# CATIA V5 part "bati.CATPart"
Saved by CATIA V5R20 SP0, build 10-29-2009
Part number: bati
Bounding box of the stored display mesh (mm): x -30 to 10, y -75 to 75, z 0 to 70
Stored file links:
  D:\Dropbox\IAO_2011\MMS_GR2\IAO_2011_1491_mcabanel\IAO_2011_1491_mcabanel\bati.CATPart
  U:\2A\IAO\Projet\ass\kin\IAO_mcabanel.CATProduct
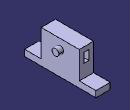
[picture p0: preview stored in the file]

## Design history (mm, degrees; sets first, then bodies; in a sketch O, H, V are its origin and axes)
Set1
  Point1: linked copy from another document
  Point2: linked copy from another document
Body1 (main body)
  Sketch1 on yz-plane, origin (0, 0, 0), H (0, 1, 0), V (0, 0, 1)
    point P1 (-75, 0)
    line L1 (-75, 0) -> (75, 0)
    line L2 (75, 0) -> (75, 13)
    line L3 (75, 13) -> (40, 13)
    line L4 (40, 13) -> (40, 70)
    line L5 (40, 70) -> (-40, 70)
    line L6 (-40, 70) -> (-40, 13)
    point P7 (-40, 13)
    line L7 (-40, 13) -> (-75, 13)
    line L8 (-75, 13) -> (-75, 0)
    distance L8 L2 = 150
    distance V L2 = 75
    distance L4 L6 = 80
    distance L4 V = 40
    distance L5 L1 = 70
    coincidence: P1 H, P7 L3
    horizontal: L1 H, L3 H, L5 H, L7 H
    vertical: L2 V, L4 V, L6 V, L8 V
  Pad1: profile Sketch1, direction (-1, 0, 0), length 30
  Sketch2 on face of Pad1 from Sketch1.L4, origin (0, 40, 0), H (-1, 0, 0), V (0, 0, 1)
    line L1 (10, 60) -> (20, 60)
    line L2 (20, 60) -> (20, 40)
    line L3 (20, 40) -> (10, 40)
    line L4 (10, 40) -> (10, 60)
    reference projected point E1 (10, 50) from Point1
    reference projected point E2 (10, 50) from Point1
    distance L3 E2 = 10
    distance L1 L3 = 20
    distance L2 L4 = 10
    horizontal: L1 H, L3 H
    vertical: L2 V, L4 V
    coincidence: L4 E1
  Pocket1: profile Sketch2, direction (0, -1, 0), length 80
  Sketch3 on start face of Pad1, origin (0, 0, 0), H (0, 1, 0), V (0, 0, 1)
    circle A1 centre (0, 50) radius 7
    point P1 (0, 50)
    reference projected point E1 (0, 50) from Point2
    radius A1 = 7
    coincidence: P1 E1
  Pad2: profile Sketch3, direction (1, 0, 0), length 10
